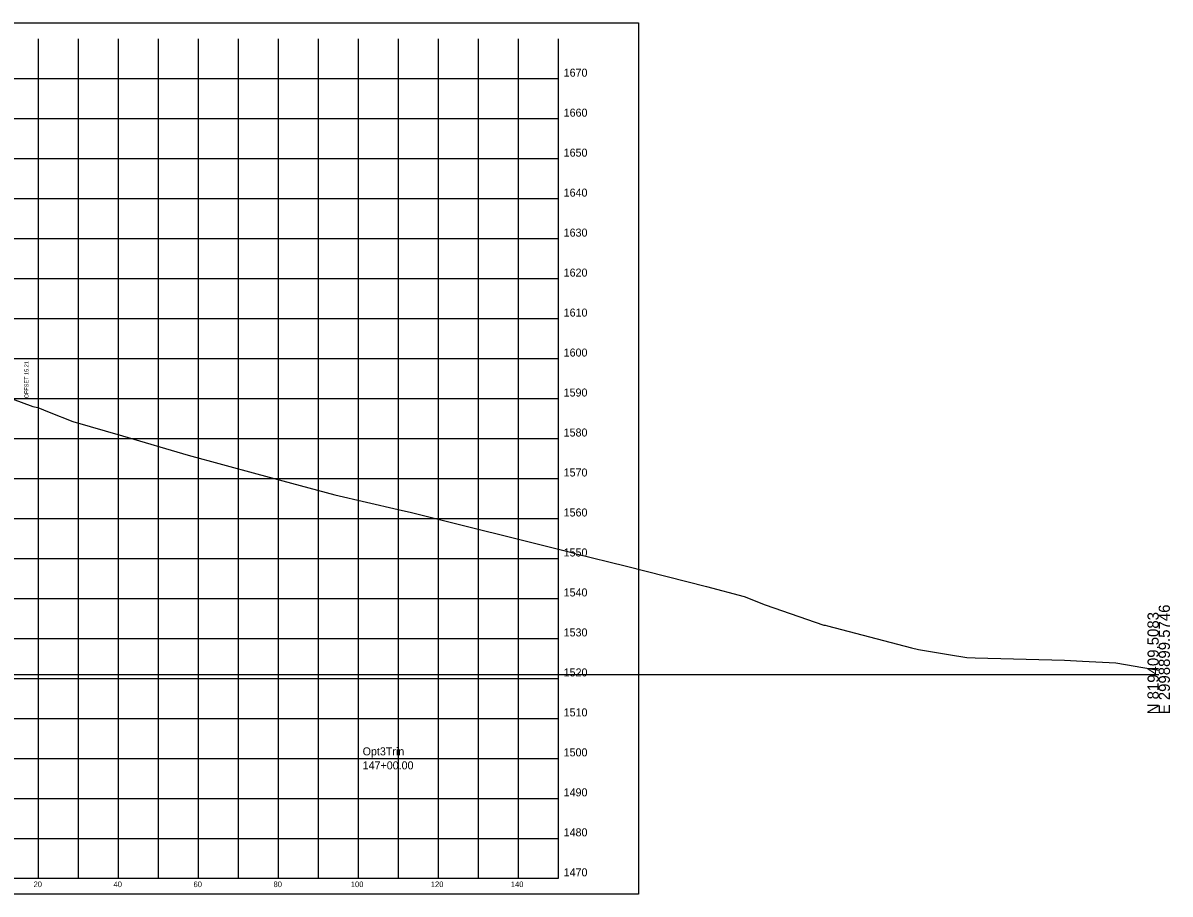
# Model space of a CAD drawing. Extents: x -26 to 603, y -10 to 4805.
# Drawn here: x 316.1 to 602.8, y 1445.1 to 1662.9 of the extents above; entities that cross this region are included whole.
import ezdxf

# ---------------------------------------------------------------- set-up
doc = ezdxf.new("R2010")
doc.units = 0
for name, color, linetype in [('DESIGN - SHEET - Corner Text', 7, 'Continuous'), ('DESIGN - SHEET - Light Grid', 7, 'Continuous'), ('DESIGN - SHEET - Linework', 7, 'Continuous'), ('DESIGN - SHEET - Plot Shape', 7, 'Continuous'), ('DESIGN - TYPICAL - Slope Tie Text', 7, 'Continuous'), ('DESIGN - TYPICAL - Warning Text', 7, 'Continuous'), ('SURVEY - GROUND - Top of Ground', 7, 'Continuous')]:
    doc.layers.add(name, color=color, linetype=linetype)

msp = doc.modelspace()

# ---------------------------------------------------------------- linework, layer by layer
at = {"layer": 'DESIGN - SHEET - Light Grid'}
msp.add_line((300, 1500), (600, 1500), dxfattribs=at)
at = {"layer": 'DESIGN - SHEET - Linework'}
for p, q in [((320, 1449), (320, 1659)), ((330, 1449), (330, 1659)), ((340, 1449), (340, 1659)), ((350, 1449), (350, 1659)), ((360, 1449), (360, 1659)), ((370, 1449), (370, 1659)), ((380, 1449), (380, 1659)), ((390, 1449), (390, 1659)), ((400, 1449), (400, 1659)), ((410, 1449), (410, 1659)), ((420, 1449), (420, 1659)), ((430, 1449), (430, 1659)), ((440, 1449), (440, 1659)), ((150, 1649), (450, 1649)), ((150, 1639), (450, 1639)), ((150, 1629), (450, 1629)), ((150, 1619), (450, 1619)), ((150, 1609), (450, 1609)), ((150, 1599), (450, 1599)), ((150, 1589), (450, 1589)), ((150, 1579), (450, 1579)), ((150, 1569), (450, 1569)), ((150, 1559), (450, 1559)), ((150, 1549), (450, 1549)), ((150, 1539), (450, 1539)), ((150, 1529), (450, 1529)), ((150, 1519), (450, 1519)), ((150, 1509), (450, 1509)), ((150, 1499), (450, 1499)), ((150, 1489), (450, 1489)), ((150, 1479), (450, 1479)), ((150, 1469), (450, 1469)), ((150, 1459), (450, 1459))]:
    msp.add_line(p, q, dxfattribs=at)
msp.add_lwpolyline([(150, 1659), (150, 1449), (450, 1449), (450, 1659)], dxfattribs=at)
at = {"layer": 'DESIGN - SHEET - Plot Shape'}
msp.add_lwpolyline([(130, 1662.94), (470, 1662.94), (470, 1445.06), (130, 1445.06)], close=True, dxfattribs=at)
at = {"layer": 'SURVEY - GROUND - Top of Ground'}
msp.add_line((413.19, 1540.5), (452.97, 1530.56), dxfattribs=at)
for points in [[(311.12, 1569.77), (318.58, 1567.03), (319.81, 1566.72), (322.6, 1565.57), (328.54, 1563.27), (340.98, 1559.71), (357.41, 1554.83), (374.53, 1550.13), (394.07, 1544.88), (409.92, 1541.28), (413.19, 1540.5)], [(452.97, 1530.56), (454.01, 1530.28), (466.94, 1527.05), (486.98, 1522), (496.39, 1519.5), (501.66, 1517.36), (516.28, 1512.33), (516.61, 1512.28), (517.22, 1512.17), (538.2, 1506.63), (539.97, 1506.19), (547.46, 1504.94), (552.03, 1504.22), (554.12, 1504.17), (576.47, 1503.58), (580.96, 1503.34), (589.29, 1502.87), (598.46, 1501.31), (600, 1501.09)]]:
    msp.add_lwpolyline(points, dxfattribs=at)

# ---------------------------------------------------------------- texts
at = {"layer": 'DESIGN - SHEET - Corner Text'}
for s, height, p in [('1670', 2, (451.25, 1649.5)), ('1660', 2, (451.25, 1639.5)), ('1650', 2, (451.25, 1629.5)), ('1640', 2, (451.25, 1619.5)), ('1630', 2, (451.25, 1609.5)), ('1620', 2, (451.25, 1599.5)), ('1610', 2, (451.25, 1589.5)), ('1600', 2, (451.25, 1579.5)), ('1590', 2, (451.25, 1569.5)), ('1580', 2, (451.25, 1559.5)), ('1570', 2, (451.25, 1549.5)), ('1560', 2, (451.25, 1539.5)), ('1550', 2, (451.25, 1529.5)), ('1540', 2, (451.25, 1519.5)), ('1530', 2, (451.25, 1509.5)), ('1520', 2, (451.25, 1499.5)), ('1510', 2, (451.25, 1489.5)), ('1500', 2, (451.25, 1479.5)), ('1490', 2, (451.25, 1469.5)), ('1480', 2, (451.25, 1459.5)), ('1470', 2, (451.25, 1449.5)), ('20', 1.4, (318.74, 1446.8)), ('40', 1.4, (338.74, 1446.8)), ('60', 1.4, (358.74, 1446.8)), ('80', 1.4, (378.74, 1446.8)), ('100', 1.4, (398.06, 1446.8)), ('120', 1.4, (418.06, 1446.8)), ('140', 1.4, (438.06, 1446.8))]:
    msp.add_text(s, height=height, dxfattribs=at).set_placement(p)
at = {"layer": 'DESIGN - SHEET - Light Grid'}
for s, p in [('E 2998899.5746', (602.8, 1490)), ('N 819409.5083', (600, 1490))]:
    msp.add_text(s, height=2.8, rotation=90, dxfattribs=at).set_placement(p)
at = {"layer": 'DESIGN - TYPICAL - Slope Tie Text'}
msp.add_text('OFFSET 15.21', height=1, rotation=90, dxfattribs=at).set_placement((317.46, 1569.06))
at = {"layer": 'DESIGN - TYPICAL - Warning Text'}
for s, p in [('Opt3Trin', (401, 1479.75)), ('147+00.00', (401, 1476.25))]:
    msp.add_text(s, height=2, dxfattribs=at).set_placement(p)

doc.saveas('drawing.dxf')
